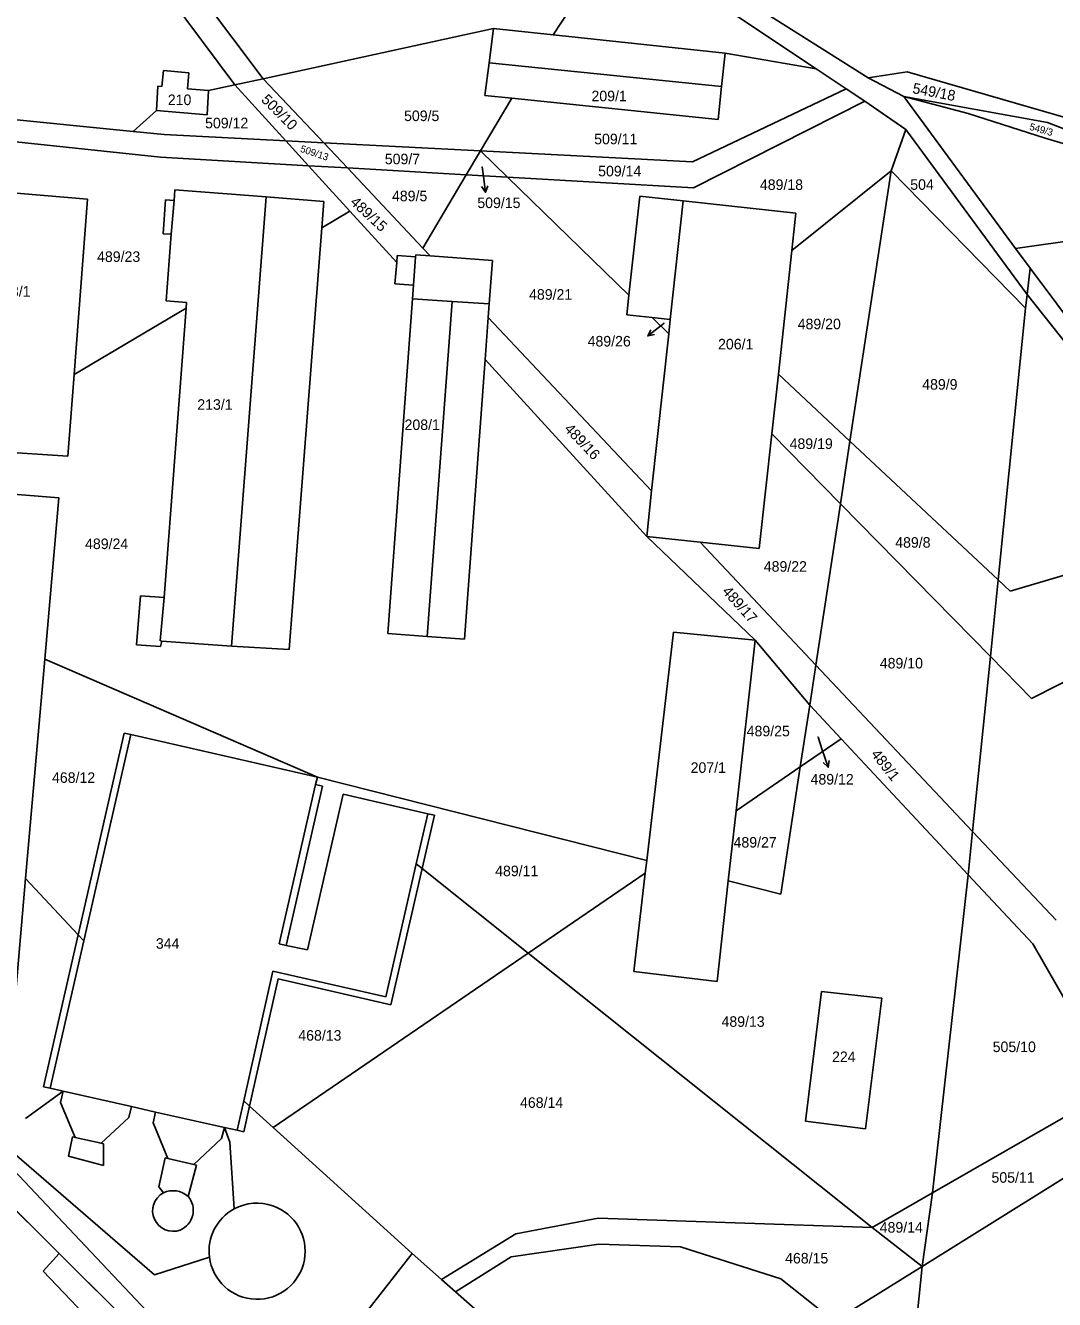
# Model space of a CAD drawing. Extents: x -593358 to -590116, y -1072518 to -1068420.
# Drawn here: x -591731.6 to -591565.8, y -1071622.8 to -1071417.5 of the extents above; entities that cross this region are included whole.
import ezdxf

# ---------------------------------------------------------------- set-up
doc = ezdxf.new("R2010")
doc.units = 0
for name, color, linetype in [('Parcela KN', 7, 'Continuous'), ('Parcela ZE', 7, 'Continuous'), ('Parcelní číslo', 7, 'Continuous'), ('Parcelní číslo_stavební', 7, 'Continuous'), ('stavby - vnitřní kresba', 7, 'Continuous'), ('Vnitřní obvod', 7, 'Continuous'), ('Vrstva 16', 7, 'Continuous')]:
    doc.layers.add(name, color=color, linetype=linetype)

msp = doc.modelspace()

# ---------------------------------------------------------------- linework, layer by layer
at = {"layer": 'Parcela KN'}
for p, q in [((-591720.81, -1071389.42), (-591693.29, -1071426.03)), ((-591711.1, -1071409.24), (-591697.88, -1071427.03)), ((-591615.57, -1071413.45), (-591595.8, -1071425.89)), ((-591604.17, -1071424.45), (-591617.67, -1071415.47)), ((-591656.21, -1071417.93), (-591693.29, -1071426.03)), ((-591656.21, -1071417.93), (-591656.9, -1071423.48)), ((-591646.56, -1071418.96), (-591656.21, -1071417.93)), ((-591618.87, -1071421.92), (-591646.56, -1071418.96)), ((-591656.9, -1071423.48), (-591657.56, -1071428.73)), ((-591619.44, -1071427.31), (-591618.87, -1071421.92)), ((-591618.87, -1071421.92), (-591604.17, -1071424.45)), ((-591709.62, -1071427.31), (-591709.4, -1071424.7)), ((-591709.4, -1071424.7), (-591705.3, -1071425.09)), ((-591705.3, -1071425.09), (-591705.51, -1071427.65)), ((-591599.37, -1071427.64), (-591604.17, -1071424.45)), ((-591595.8, -1071425.89), (-591589.54, -1071424.92)), ((-591589.54, -1071424.92), (-591521.53, -1071444.56)), ((-591714.28, -1071434.53), (-591800.79, -1071425.82)), ((-591710.52, -1071431.15), (-591710.27, -1071427.24)), ((-591710.27, -1071427.24), (-591709.62, -1071427.31)), ((-591705.51, -1071427.65), (-591702.1, -1071427.95)), ((-591697.88, -1071427.03), (-591702.1, -1071427.95)), ((-591693.29, -1071426.03), (-591697.88, -1071427.03)), ((-591599.37, -1071427.64), (-591624.14, -1071439.43)), ((-591619.99, -1071432.61), (-591619.44, -1071427.31)), ((-591596.32, -1071429.67), (-591599.37, -1071427.64)), ((-591595.8, -1071425.89), (-591590.08, -1071428.9)), ((-591702.1, -1071427.95), (-591702.34, -1071431.84)), ((-591657.56, -1071428.73), (-591653.25, -1071429.17)), ((-591653.25, -1071429.17), (-591619.99, -1071432.61)), ((-591596.32, -1071429.67), (-591623.95, -1071443.63)), ((-591589.75, -1071434.24), (-591596.32, -1071429.67)), ((-591579.66, -1071431.63), (-591590.08, -1071428.9)), ((-591590.08, -1071428.9), (-591572.04, -1071453.42)), ((-591710.52, -1071431.15), (-591714.28, -1071434.53)), ((-591702.34, -1071431.84), (-591710.52, -1071431.15)), ((-591567.29, -1071435.59), (-591579.66, -1071431.63)), ((-591709.87, -1071438.67), (-591755.69, -1071433.79)), ((-591709.29, -1071435.03), (-591714.28, -1071434.53)), ((-591689.65, -1071436.04), (-591709.29, -1071435.03)), ((-591683.55, -1071436.36), (-591689.65, -1071436.04)), ((-591589.75, -1071434.24), (-591592.1, -1071440.86)), ((-591570.2, -1071460.82), (-591589.75, -1071434.24)), ((-591539.2, -1071443.97), (-591567.29, -1071435.59)), ((-591658.29, -1071437.67), (-591683.55, -1071436.36)), ((-591624.14, -1071439.43), (-591658.29, -1071437.67)), ((-591686, -1071440.05), (-591709.87, -1071438.67)), ((-591679.74, -1071440.41), (-591686, -1071440.05)), ((-591660.57, -1071441.52), (-591679.74, -1071440.41)), ((-591653.93, -1071441.9), (-591660.57, -1071441.52)), ((-591623.95, -1071443.63), (-591653.93, -1071441.9)), ((-591592.1, -1071440.86), (-591598.74, -1071484.43)), ((-591592.1, -1071440.86), (-591570.42, -1071463.02)), ((-591746.38, -1071443.36), (-591721.61, -1071445.45)), ((-591707.53, -1071443.96), (-591707.68, -1071445.67)), ((-591692.81, -1071445.08), (-591707.53, -1071443.96)), ((-591721.61, -1071445.45), (-591723.78, -1071473.73)), ((-591709.03, -1071445.57), (-591709.45, -1071451.01)), ((-591707.68, -1071445.67), (-591709.03, -1071445.57)), ((-591683.55, -1071445.8), (-591692.81, -1071445.08)), ((-591683.88, -1071450.05), (-591683.55, -1071445.8)), ((-591632.61, -1071444.95), (-591634.35, -1071460.91)), ((-591625.6, -1071445.71), (-591632.61, -1071444.95)), ((-591607.45, -1071447.69), (-591625.6, -1071445.71)), ((-591608.11, -1071453.7), (-591607.45, -1071447.69)), ((-591689.14, -1071518.03), (-591683.88, -1071450.05)), ((-591709.45, -1071451.01), (-591708.13, -1071451.11)), ((-591708.13, -1071451.11), (-591708.95, -1071461.84)), ((-591671.69, -1071454.5), (-591671.79, -1071455.63)), ((-591668.76, -1071454.76), (-591671.69, -1071454.5)), ((-591668.73, -1071454.41), (-591668.76, -1071454.76)), ((-591666.38, -1071454.59), (-591668.73, -1071454.41)), ((-591610.28, -1071473.64), (-591608.11, -1071453.7)), ((-591572.04, -1071453.42), (-591569.71, -1071456.59)), ((-591671.79, -1071455.63), (-591672.1, -1071459.07)), ((-591656.36, -1071455.35), (-591666.38, -1071454.59)), ((-591656.87, -1071462.32), (-591656.36, -1071455.35)), ((-591570.2, -1071460.82), (-591569.71, -1071456.59)), ((-591569.71, -1071456.59), (-591559.09, -1071470.75)), ((-591672.1, -1071459.07), (-591669.09, -1071459.3)), ((-591669.09, -1071459.3), (-591669.25, -1071461.52)), ((-591708.95, -1071461.84), (-591705.66, -1071462.09)), ((-591705.66, -1071462.09), (-591705.73, -1071463.02)), ((-591669.25, -1071461.52), (-591673.21, -1071515.44)), ((-591657.03, -1071464.51), (-591656.87, -1071462.32)), ((-591634.35, -1071460.91), (-591634.7, -1071464.09)), ((-591570.42, -1071463.02), (-591570.2, -1071460.82)), ((-591570.2, -1071460.82), (-591559.79, -1071473.91)), ((-591705.73, -1071463.02), (-591709.29, -1071509.66)), ((-591657.53, -1071471.26), (-591657.03, -1071464.51)), ((-591634.7, -1071464.09), (-591630.62, -1071464.54)), ((-591630.62, -1071464.54), (-591627.69, -1071464.86)), ((-591574.86, -1071506.78), (-591570.42, -1071463.02)), ((-591627.69, -1071464.86), (-591627.94, -1071467.14)), ((-591627.94, -1071467.14), (-591630.7, -1071492.45)), ((-591660.85, -1071516.38), (-591657.53, -1071471.26)), ((-591723.78, -1071473.73), (-591724.78, -1071486.84)), ((-591611.33, -1071483.27), (-591610.28, -1071473.64)), ((-591613.35, -1071501.77), (-591611.33, -1071483.27)), ((-591598.74, -1071484.43), (-591600.28, -1071494.53)), ((-591724.78, -1071486.84), (-591743.85, -1071485.64)), ((-591726.25, -1071493.56), (-591744.87, -1071492.1)), ((-591630.7, -1071492.45), (-591631.5, -1071499.79)), ((-591728.52, -1071519.61), (-591726.25, -1071493.56)), ((-591600.28, -1071494.53), (-591604.24, -1071520.53)), ((-591631.5, -1071499.79), (-591622.9, -1071500.73)), ((-591622.9, -1071500.73), (-591613.35, -1071501.77)), ((-591576.11, -1071519.16), (-591574.86, -1071506.78)), ((-591713.06, -1071509.36), (-591713.72, -1071517.29)), ((-591709.29, -1071509.66), (-591713.06, -1071509.36)), ((-591673.21, -1071515.44), (-591666.88, -1071515.92)), ((-591666.88, -1071515.92), (-591660.85, -1071516.38)), ((-591627.19, -1071515.23), (-591631.49, -1071552.01)), ((-591614.02, -1071516.53), (-591627.19, -1071515.23)), ((-591713.72, -1071517.29), (-591709.86, -1071517.52)), ((-591709.86, -1071517.52), (-591709.67, -1071516.66)), ((-591709.67, -1071516.66), (-591698.42, -1071517.49)), ((-591698.42, -1071517.49), (-591689.14, -1071518.03)), ((-591617.08, -1071544.03), (-591614.02, -1071516.53)), ((-591731.6, -1071554.93), (-591728.52, -1071519.61)), ((-591728.52, -1071519.61), (-591684.58, -1071538.61)), ((-591578.96, -1071547.35), (-591576.11, -1071519.16)), ((-591604.24, -1071520.53), (-591605.22, -1071526.98)), ((-591605.22, -1071526.98), (-591606.74, -1071536.95)), ((-591722.22, -1071564.99), (-591714.64, -1071531.75)), ((-591714.64, -1071531.75), (-591684.58, -1071538.61)), ((-591684.58, -1071538.61), (-591684.85, -1071539.8)), ((-591631.49, -1071552.01), (-591684.58, -1071538.61)), ((-591606.74, -1071536.95), (-591609.86, -1071557.47)), ((-591684.85, -1071539.8), (-591690.73, -1071565.48)), ((-591686.17, -1071566.45), (-591680.44, -1071541.35)), ((-591680.44, -1071541.35), (-591666.78, -1071544.49)), ((-591666.78, -1071544.49), (-591668.63, -1071552.56)), ((-591618.34, -1071555.33), (-591617.08, -1071544.03)), ((-591579.67, -1071554.32), (-591578.96, -1071547.35)), ((-591668.63, -1071552.56), (-591673.53, -1071573.98)), ((-591667.68, -1071553.32), (-591668.63, -1071552.56)), ((-591631.49, -1071552.01), (-591631.73, -1071554.05)), ((-591733.41, -1071575.63), (-591731.6, -1071554.93)), ((-591650.59, -1071566.95), (-591667.68, -1071553.32)), ((-591631.73, -1071554.05), (-591633.59, -1071569.91)), ((-591585.46, -1071605.59), (-591579.67, -1071554.32)), ((-591620.15, -1071571.55), (-591618.34, -1071555.33)), ((-591609.86, -1071557.47), (-591618.34, -1071555.33)), ((-591727.63, -1071588.75), (-591722.22, -1071564.99)), ((-591690.73, -1071565.48), (-591689.6, -1071565.72)), ((-591689.6, -1071565.72), (-591686.17, -1071566.45)), ((-591595.18, -1071611.16), (-591650.59, -1071566.95)), ((-591691.78, -1071569.86), (-591696.43, -1071590.79)), ((-591673.53, -1071573.98), (-591691.78, -1071569.86)), ((-591633.59, -1071569.91), (-591620.15, -1071571.55)), ((-591605.92, -1071594.07), (-591603.34, -1071573.17)), ((-591603.34, -1071573.17), (-591593.61, -1071574.21)), ((-591593.61, -1071574.21), (-591596.23, -1071595.28)), ((-591726.18, -1071615.37), (-591761.82, -1071579.99)), ((-591747.6, -1071587.08), (-591681.67, -1071656.75)), ((-591725.54, -1071589.22), (-591727.63, -1071588.75)), ((-591714.52, -1071591.7), (-591725.54, -1071589.22)), ((-591710.64, -1071592.57), (-591714.52, -1071591.7)), ((-591696.43, -1071590.79), (-591697.48, -1071595.52)), ((-591699.56, -1071595.05), (-591710.64, -1071592.57)), ((-591596.23, -1071595.28), (-591605.92, -1071594.07)), ((-591697.48, -1071595.52), (-591699.56, -1071595.05)), ((-591587.1, -1071617.45), (-591585.46, -1071605.59)), ((-591587.1, -1071617.45), (-591595.18, -1071611.16)), ((-591707.49, -1071633.93), (-591726.18, -1071615.37)), ((-591587.1, -1071617.45), (-591589.01, -1071636.06))]:
    msp.add_line(p, q, dxfattribs=at)
at = {"layer": 'Parcela ZE'}
for p, q in [((-591638.9, -1071407.28), (-591646.56, -1071418.96)), ((-591689.65, -1071436.04), (-591697.88, -1071427.03)), ((-591683.55, -1071436.36), (-591693.29, -1071426.03)), ((-591653.25, -1071429.17), (-591658.29, -1071437.67)), ((-591566.91, -1071433.09), (-591590.08, -1071428.9)), ((-591539.2, -1071443.97), (-591566.91, -1071433.09)), ((-591686, -1071440.05), (-591689.65, -1071436.04)), ((-591679.74, -1071440.41), (-591683.55, -1071436.36)), ((-591658.29, -1071437.67), (-591660.57, -1071441.52)), ((-591658.29, -1071437.67), (-591653.93, -1071441.9)), ((-591679.34, -1071447.36), (-591686, -1071440.05)), ((-591667.58, -1071453.32), (-591679.74, -1071440.41)), ((-591660.57, -1071441.52), (-591667.58, -1071453.32)), ((-591653.93, -1071441.9), (-591634.35, -1071460.91)), ((-591592.1, -1071440.86), (-591608.11, -1071453.7)), ((-591679.34, -1071447.36), (-591683.88, -1071450.05)), ((-591671.79, -1071455.63), (-591679.34, -1071447.36)), ((-591555.17, -1071451), (-591572.04, -1071453.42)), ((-591666.38, -1071454.59), (-591667.58, -1071453.32)), ((-591705.73, -1071463.02), (-591723.78, -1071473.73)), ((-591630.7, -1071492.45), (-591657.03, -1071464.51)), ((-591630.62, -1071464.54), (-591627.94, -1071467.14)), ((-591631.5, -1071499.79), (-591657.53, -1071471.26)), ((-591598.74, -1071484.43), (-591610.28, -1071473.64)), ((-591611.33, -1071483.27), (-591600.28, -1071494.53)), ((-591574.86, -1071506.78), (-591598.74, -1071484.43)), ((-591600.28, -1071494.53), (-591576.11, -1071519.16)), ((-591614.02, -1071516.53), (-591631.5, -1071499.79)), ((-591604.24, -1071520.53), (-591622.9, -1071500.73)), ((-591553.77, -1071502.98), (-591572.91, -1071508.6)), ((-591572.91, -1071508.6), (-591574.86, -1071506.78)), ((-591605.22, -1071526.98), (-591614.02, -1071516.53)), ((-591576.11, -1071519.16), (-591569.47, -1071525.92)), ((-591578.96, -1071547.35), (-591604.24, -1071520.53)), ((-591569.47, -1071525.92), (-591558.52, -1071520.39)), ((-591605.22, -1071526.98), (-591600.13, -1071532.43)), ((-591606.74, -1071536.95), (-591600.13, -1071532.43)), ((-591600.13, -1071532.43), (-591579.67, -1071554.32)), ((-591617.08, -1071544.03), (-591606.74, -1071536.95)), ((-591565.49, -1071561.65), (-591578.96, -1071547.35)), ((-591723.12, -1071564.02), (-591731.6, -1071554.93)), ((-591650.59, -1071566.95), (-591631.73, -1071554.05)), ((-591569.28, -1071565.49), (-591579.67, -1071554.32)), ((-591722.22, -1071564.99), (-591723.12, -1071564.02)), ((-591691.7, -1071595.08), (-591650.59, -1071566.95)), ((-591555.98, -1071588.69), (-591569.28, -1071565.49)), ((-591585.46, -1071605.59), (-591555.98, -1071588.69)), ((-591695.49, -1071591.64), (-591696.43, -1071590.79)), ((-591691.7, -1071595.08), (-591695.49, -1071591.64)), ((-591669.31, -1071615.4), (-591691.7, -1071595.08)), ((-591587.1, -1071617.45), (-591555.33, -1071597.66)), ((-591595.18, -1071611.16), (-591585.46, -1071605.59)), ((-591652.58, -1071612.19), (-591639.34, -1071609.67)), ((-591639.34, -1071609.67), (-591595.18, -1071611.16)), ((-591664.59, -1071619.55), (-591652.58, -1071612.19)), ((-591639.19, -1071613.87), (-591653.33, -1071615.91)), ((-591626.06, -1071614.28), (-591639.19, -1071613.87)), ((-591609.88, -1071619.44), (-591626.06, -1071614.28)), ((-591726.18, -1071615.37), (-591728.76, -1071618.23)), ((-591690.59, -1071642.53), (-591669.31, -1071615.4)), ((-591669.31, -1071615.4), (-591664.59, -1071619.55)), ((-591653.33, -1071615.91), (-591662.32, -1071621.54)), ((-591728.76, -1071618.23), (-591710.75, -1071637.02)), ((-591601.29, -1071626.28), (-591587.1, -1071617.45)), ((-591664.59, -1071619.55), (-591662.32, -1071621.54)), ((-591601.29, -1071626.28), (-591609.88, -1071619.44)), ((-591662.32, -1071621.54), (-591652.94, -1071629.78))]:
    msp.add_line(p, q, dxfattribs=at)
at = {"layer": 'stavby - vnitřní kresba'}
for p, q in [((-591656.9, -1071423.48), (-591619.44, -1071427.31)), ((-591707.68, -1071445.67), (-591708.13, -1071451.11)), ((-591698.42, -1071517.49), (-591692.81, -1071445.08)), ((-591625.6, -1071445.71), (-591627.69, -1071464.86)), ((-591668.76, -1071454.76), (-591669.09, -1071459.3)), ((-591669.25, -1071461.52), (-591662.86, -1071461.93)), ((-591662.86, -1071461.93), (-591666.88, -1071515.92)), ((-591662.86, -1071461.93), (-591656.87, -1071462.32)), ((-591709.29, -1071509.66), (-591709.89, -1071516.63)), ((-591709.67, -1071516.66), (-591709.89, -1071516.63)), ((-591715.71, -1071531.5), (-591723.12, -1071564.02)), ((-591714.64, -1071531.75), (-591715.71, -1071531.5)), ((-591683.73, -1071540.06), (-591689.6, -1071565.72)), ((-591684.85, -1071539.8), (-591683.73, -1071540.06)), ((-591665.71, -1071544.73), (-591667.68, -1071553.32)), ((-591666.78, -1071544.49), (-591665.71, -1071544.73)), ((-591667.68, -1071553.32), (-591672.71, -1071575.3)), ((-591723.12, -1071564.02), (-591728.7, -1071588.51)), ((-591690.92, -1071571.08), (-591695.49, -1071591.64)), ((-591672.71, -1071575.3), (-591690.92, -1071571.08)), ((-591747.6, -1071587.08), (-591710.8, -1071618.83)), ((-591731.64, -1071593.61), (-591725.54, -1071589.22)), ((-591728.7, -1071588.51), (-591727.63, -1071588.75)), ((-591725.54, -1071589.22), (-591725.96, -1071591.01)), ((-591725.96, -1071591.01), (-591723.6, -1071596.66)), ((-591714.97, -1071593.47), (-591714.52, -1071591.7)), ((-591695.49, -1071591.64), (-591696.41, -1071595.76)), ((-591719.42, -1071597.6), (-591714.97, -1071593.47)), ((-591710.64, -1071592.57), (-591711.04, -1071594.34)), ((-591711.04, -1071594.34), (-591708.69, -1071600.04)), ((-591700.04, -1071596.85), (-591699.56, -1071595.05)), ((-591698.68, -1071597.43), (-591699.56, -1071595.05)), ((-591696.41, -1071595.76), (-591697.48, -1071595.52)), ((-591724.05, -1071596.57), (-591724.69, -1071599.71)), ((-591723.6, -1071596.66), (-591724.05, -1071596.57)), ((-591719.42, -1071597.6), (-591723.6, -1071596.66)), ((-591719.02, -1071597.72), (-591719.42, -1071597.6)), ((-591719.06, -1071601.19), (-591719.02, -1071597.72)), ((-591704.5, -1071601.01), (-591700.04, -1071596.85)), ((-591698, -1071608.19), (-591698.68, -1071597.43)), ((-591724.69, -1071599.71), (-591719.06, -1071601.19)), ((-591709.12, -1071599.93), (-591710.14, -1071604.65)), ((-591708.69, -1071600.04), (-591709.12, -1071599.93)), ((-591708.69, -1071600.04), (-591704.5, -1071601.01)), ((-591704.07, -1071601.12), (-591705.4, -1071606.18)), ((-591704.5, -1071601.01), (-591704.07, -1071601.12)), ((-591710.14, -1071604.65), (-591709.39, -1071605.59)), ((-591701.97, -1071615.95), (-591710.8, -1071618.83))]:
    msp.add_line(p, q, dxfattribs=at)
for centre, radius, start, end in [((-591707.826, -1071608.494), 3.298, 118.31074, 290.14475), ((-591707.843, -1071608.915), 3.667, 48.22482, 114.95247), ((-591708.02, -1071608.414), 3.443, 292.7237, 40.45313), ((-591694.303, -1071614.977), 7.728, 118.57731, 187.23431), ((-591694.285, -1071615.008), 7.742, 186.98516, 70.96131), ((-591694.319, -1071614.947), 7.695, 70.57946, 118.58298)]:
    msp.add_arc(centre, radius, start, end, dxfattribs=at)
at = {"layer": 'Vnitřní obvod'}
for p, q in [((-591610.92, -1071419.96), (-591617.67, -1071415.47)), ((-591604.17, -1071424.45), (-591610.92, -1071419.96)), ((-591601.77, -1071426.045), (-591604.17, -1071424.45)), ((-591599.37, -1071427.64), (-591601.77, -1071426.045)), ((-591596.32, -1071429.67), (-591599.37, -1071427.64)), ((-591593.035, -1071431.955), (-591596.32, -1071429.67)), ((-591589.75, -1071434.24), (-591593.035, -1071431.955)), ((-591574.86, -1071506.78), (-591570.42, -1071463.02)), ((-591576.11, -1071519.16), (-591574.86, -1071506.78)), ((-591578.96, -1071547.35), (-591576.11, -1071519.16)), ((-591579.67, -1071554.32), (-591578.96, -1071547.35)), ((-591585.46, -1071605.59), (-591579.67, -1071554.32)), ((-591744, -1071597.68), (-591726.18, -1071615.37)), ((-591587.1, -1071617.45), (-591585.46, -1071605.59)), ((-591726.18, -1071615.37), (-591716.835, -1071624.65)), ((-591589.01, -1071636.06), (-591587.1, -1071617.45))]:
    msp.add_line(p, q, dxfattribs=at)
msp.add_lwpolyline([(-591570.42, -1071463.02), (-591592.1, -1071440.86), (-591589.75, -1071434.24)], dxfattribs=at)
at = {"layer": 'Vrstva 16'}
for p, q in [((-591658, -1071440.25), (-591657.86, -1071441.35)), ((-591657.488, -1071444.327), (-591657.86, -1071441.35)), ((-591631.333, -1071467.495), (-591628.96, -1071465.66)), ((-591628.69, -1071465.45), (-591628.96, -1071465.66)), ((-591603.88, -1071532.14), (-591603.2, -1071534.17)), ((-591602.244, -1071537.014), (-591603.2, -1071534.17))]:
    msp.add_line(p, q, dxfattribs=at)
for points in [[(-591657.116, -1071443.272), (-591657.488, -1071444.327), (-591658.108, -1071443.397)], [(-591630.236, -1071467.279), (-591631.333, -1071467.495), (-591630.848, -1071466.488)], [(-591602.089, -1071535.906), (-591602.244, -1071537.014), (-591603.036, -1071536.225)]]:
    msp.add_lwpolyline(points, dxfattribs=at)

# ---------------------------------------------------------------- texts
at = {"layer": 'Parcelní číslo'}
for s, height, rotation, p in [('549/18', 1.7, 349.27507, (-591588.754, -1071428.345)), ('509/10', 1.7, 315.01219, (-591693.74, -1071429.551)), ('549/3', 1.14, 344.40493, (-591569.894, -1071434.257)), ('509/13', 1.14, 341.42555, (-591687.431, -1071437.779)), ('489/15', 1.7, 317.13214, (-591679.4, -1071446.092)), ('489/16', 1.7, 313.69439, (-591644.886, -1071482.582)), ('489/17', 1.7, 311.80363, (-591619.437, -1071508.736)), ('489/1', 1.7, 308.02211, (-591595.437, -1071534.929))]:
    msp.add_text(s, height=height, rotation=rotation, dxfattribs=at).set_placement(p)
for s, height, p in [('509/5', 1.7, (-591670.604, -1071432.86)), ('509/12', 1.7, (-591702.672, -1071434.03)), ('509/11', 1.7, (-591639.96, -1071436.6)), ('509/7', 1.7, (-591673.707, -1071439.82)), ('509/15', 0.1, (-591658.229, -1071440.25)), ('509/14', 1.7, (-591639.318, -1071441.77)), ('489/18', 1.7, (-591613.251, -1071443.96)), ('504', 1.7, (-591589.018, -1071443.94)), ('489/5', 1.7, (-591672.547, -1071445.78)), ('489/23', 1.7, (-591720.08, -1071455.56)), ('489/21', 1.7, (-591650.455, -1071461.65)), ('489/20', 1.7, (-591607.16, -1071466.41)), ('489/26', 0.1, (-591628.938, -1071465.45)), ('489/9', 1.7, (-591587.09, -1071476.15)), ('489/19', 1.7, (-591608.461, -1071485.71)), ('489/24', 1.7, (-591722.013, -1071501.84)), ('489/8', 1.7, (-591591.44, -1071501.62)), ('489/22', 1.7, (-591612.626, -1071505.49)), ('489/10', 1.7, (-591593.928, -1071521.08)), ('489/25', 1.7, (-591615.38, -1071532.02)), ('489/12', 0.1, (-591604.108, -1071532.14)), ('468/12', 1.7, (-591727.345, -1071539.52)), ('489/27', 1.7, (-591617.493, -1071549.95)), ('489/11', 1.7, (-591655.923, -1071554.56)), ('489/13', 1.7, (-591619.438, -1071578.84)), ('468/13', 1.7, (-591687.648, -1071581.07)), ('505/10', 1.7, (-591575.732, -1071582.91)), ('468/14', 1.7, (-591651.911, -1071591.9)), ('505/11', 1.7, (-591575.927, -1071603.97)), ('489/14', 1.7, (-591593.941, -1071612.01)), ('468/15', 1.7, (-591609.188, -1071616.98))]:
    msp.add_text(s, height=height, dxfattribs=at).set_placement(p)
at = {"layer": 'Parcelní číslo_stavební'}
for s, p in [('210', (-591708.677, -1071430.28)), ('209/1', (-591640.396, -1071429.67)), ('293/1', (-591736.496, -1071461.16)), ('206/1', (-591619.996, -1071469.66)), ('213/1', (-591703.928, -1071479.39)), ('208/1', (-591670.522, -1071482.65)), ('207/1', (-591624.415, -1071537.91)), ('344', (-591710.601, -1071566.26)), ('224', (-591601.621, -1071584.52))]:
    msp.add_text(s, height=1.7, dxfattribs=at).set_placement(p)
at = {"layer": 'Vrstva 16'}
for s, p in [('509/15', (-591658.793, -1071446.88)), ('489/26', (-591641.014, -1071469.19)), ('489/12', (-591605.083, -1071539.79))]:
    msp.add_text(s, height=1.7, dxfattribs=at).set_placement(p)

doc.saveas('drawing.dxf')
